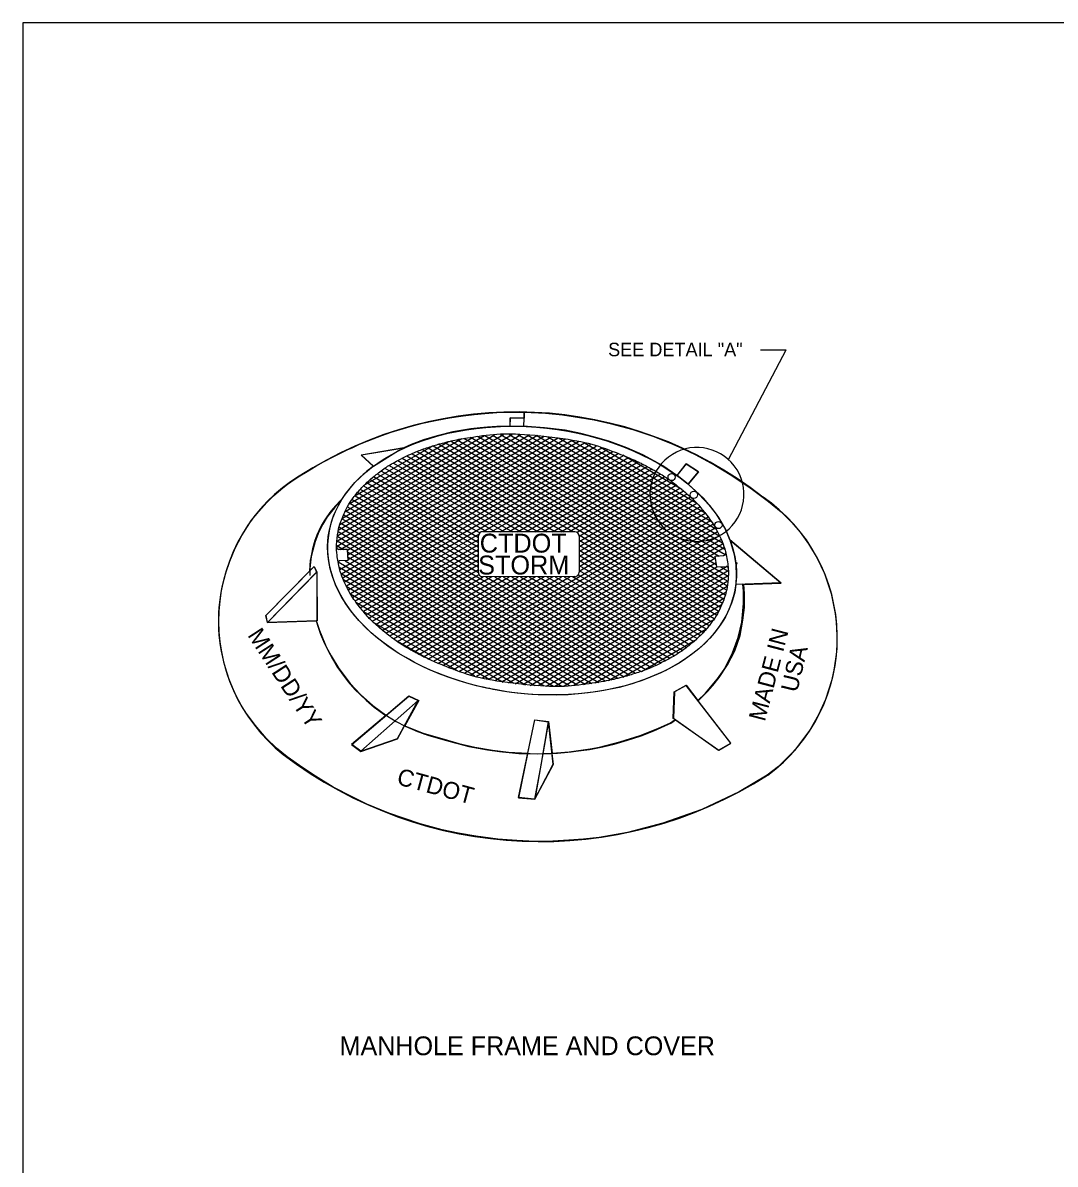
# Model space of a CAD drawing. Extents: x 0 to 31.8, y -0.5 to 20.8.
# Drawn here: x 0 to 9.62, y 10.11 to 20.75 of the extents above; entities that cross this region are included whole.
import ezdxf

# ---------------------------------------------------------------- set-up
doc = ezdxf.new("R2010")
doc.units = 0
for name, color, linetype in [('CT_Border_Perimeter_Shape', 7, 'Continuous'), ('CT_CSHT_GeneralLabel', 7, 'Continuous'), ('CT_Dimensions', 7, 'Continuous'), ('sb_Existing Structural Steel', 7, 'Continuous')]:
    doc.layers.add(name, color=color, linetype=linetype)

msp = doc.modelspace()

# ---------------------------------------------------------------- linework, layer by layer
at = {"layer": 'CT_Border_Perimeter_Shape'}
msp.add_lwpolyline([(0, 0), (31.75, 0), (31.75, 20.75), (0, 20.75)], close=True, dxfattribs=at)
at = {"layer": 'CT_Dimensions'}
for p in [(6.575, 16.68), (6.873, 17.702)]:
    msp.add_line(p, (7.113, 17.702), dxfattribs=at)
msp.add_arc((6.282, 16.354), 0.438, 31.4791, 31.418, dxfattribs=at)
at = {"layer": 'sb_Existing Structural Steel'}
for p, q in [((2.924, 15.869), (4.715, 16.908)), ((2.933, 15.923), (4.637, 16.911)), ((2.936, 15.97), (4.561, 16.913)), ((2.94, 16.02), (4.479, 16.912)), ((2.953, 16.073), (4.396, 16.91)), ((2.953, 15.654), (5.056, 16.873)), ((2.957, 15.841), (4.795, 16.907)), ((2.969, 15.614), (5.118, 16.861)), ((2.978, 16.134), (4.302, 16.902)), ((2.982, 15.576), (5.178, 16.849)), ((2.997, 15.538), (5.235, 16.835)), ((3.004, 16.196), (4.198, 16.888)), ((3.015, 15.501), (5.289, 16.82)), ((3.026, 15.836), (4.859, 16.898)), ((3.029, 15.791), (4.926, 16.892)), ((3.033, 15.746), (4.99, 16.881)), ((3.042, 16.265), (4.092, 16.874)), ((3.094, 16.342), (3.966, 16.847)), ((3.877, 16.822), (5.72, 15.756)), ((3.934, 16.837), (5.717, 15.806)), ((3.992, 16.852), (6.536, 15.379)), ((4.048, 16.864), (6.542, 15.422)), ((4.111, 16.877), (6.344, 15.585)), ((4.173, 16.887), (6.47, 15.558)), ((4.236, 16.896), (6.514, 15.578)), ((4.306, 16.902), (6.572, 15.591)), ((4.378, 16.908), (6.462, 15.702)), ((4.451, 16.913), (6.456, 15.753)), ((4.532, 16.913), (6.49, 15.78)), ((4.612, 16.913), (6.546, 15.794)), ((4.7, 16.909), (6.541, 15.844)), ((4.783, 16.908), (6.52, 15.903)), ((4.891, 16.892), (6.495, 15.965)), ((4.991, 16.881), (6.457, 16.033)), ((5.109, 16.86), (6.419, 16.102)), ((5.234, 16.834), (6.358, 16.184)), ((3.034, 15.464), (5.344, 16.804)), ((3.176, 16.436), (3.813, 16.805)), ((3.58, 16.713), (4.8, 16.007)), ((3.628, 16.734), (4.886, 16.006)), ((3.674, 16.754), (4.962, 16.009)), ((3.723, 16.772), (5.046, 16.006)), ((3.772, 16.79), (5.126, 16.007)), ((3.778, 15.851), (5.396, 16.789)), ((3.823, 16.807), (5.737, 15.7)), ((3.86, 15.853), (5.448, 16.773)), ((3.939, 15.851), (5.498, 16.755)), ((4.289, 16.007), (5.548, 16.737)), ((4.37, 16.007), (5.596, 16.718)), ((5.384, 16.794), (6.273, 16.28)), ((5.59, 16.722), (6.14, 16.404)), ((3.373, 16.6), (4.398, 16.007)), ((3.413, 16.624), (4.481, 16.007)), ((3.455, 16.647), (4.563, 16.006)), ((3.495, 16.67), (4.639, 16.009)), ((3.536, 16.693), (4.718, 16.008)), ((4.45, 16.006), (5.644, 16.699)), ((4.531, 16.007), (5.689, 16.678)), ((4.61, 16.006), (5.733, 16.657)), ((4.694, 16.007), (5.778, 16.636)), ((4.774, 16.006), (5.819, 16.613)), ((3.269, 16.52), (4.247, 15.954)), ((3.303, 16.547), (4.258, 15.995)), ((3.342, 16.572), (4.32, 16.007)), ((4.852, 16.007), (5.861, 16.592)), ((4.936, 16.006), (5.906, 16.569)), ((5.013, 16.006), (5.942, 16.545)), ((5.095, 16.007), (5.978, 16.519)), ((5.165, 16.001), (6.017, 16.495)), ((3.145, 16.404), (4.245, 15.768)), ((3.175, 16.433), (4.245, 15.815)), ((3.204, 16.464), (4.246, 15.861)), ((3.24, 16.489), (4.246, 15.907)), ((5.183, 15.916), (6.089, 16.441)), ((5.183, 15.868), (6.123, 16.414)), ((5.184, 15.964), (6.054, 16.469)), ((5.186, 15.825), (6.157, 16.388)), ((3.07, 16.306), (4.246, 15.627)), ((3.097, 16.34), (4.245, 15.676)), ((3.119, 16.372), (4.245, 15.721)), ((5.183, 15.682), (6.25, 16.3)), ((5.185, 15.73), (6.222, 16.331)), ((5.186, 15.778), (6.188, 16.359)), ((3.01, 16.201), (4.064, 15.591)), ((3.025, 16.239), (4.133, 15.598)), ((3.047, 16.273), (4.277, 15.561)), ((5.185, 15.638), (6.28, 16.273)), ((5.224, 15.61), (6.312, 16.241)), ((5.303, 15.613), (6.334, 16.211)), ((5.386, 15.613), (6.36, 16.178)), ((2.962, 16.087), (3.815, 15.593)), ((2.977, 16.127), (3.88, 15.604)), ((2.992, 16.165), (4.038, 15.559)), ((5.454, 15.604), (6.387, 16.145)), ((5.538, 15.607), (6.407, 16.111)), ((5.619, 15.607), (6.43, 16.077)), ((2.935, 15.963), (5.304, 14.593)), ((2.939, 16.008), (5.369, 14.602)), ((2.952, 16.048), (5.428, 14.615)), ((3.657, 15.641), (4.249, 15.984)), ((4.118, 14.69), (6.453, 16.044)), ((4.173, 14.674), (6.473, 16.008)), ((4.228, 14.659), (6.491, 15.971)), ((4.246, 15.627), (4.245, 15.967)), ((4.285, 16.007), (5.144, 16.007)), ((5.185, 15.966), (5.184, 15.628)), ((5.186, 15.973), (5.708, 15.671)), ((2.925, 15.877), (2.987, 15.841)), ((2.928, 15.921), (5.239, 14.584)), ((3.055, 15.432), (3.792, 15.859)), ((3.075, 15.397), (3.915, 15.884)), ((3.098, 15.363), (3.992, 15.882)), ((3.606, 15.517), (4.246, 15.888)), ((3.641, 15.585), (4.245, 15.935)), ((4.283, 14.645), (6.376, 15.859)), ((4.342, 14.631), (6.521, 15.895)), ((4.405, 14.622), (6.537, 15.858)), ((5.184, 15.927), (5.728, 15.612)), ((5.186, 15.879), (5.68, 15.594)), ((6.372, 15.857), (6.505, 15.934)), ((3.024, 15.841), (2.946, 15.842)), ((3.033, 15.738), (3.024, 15.841)), ((3.027, 15.818), (5.17, 14.578)), ((3.031, 15.768), (5.095, 14.573)), ((3.196, 15.233), (4.244, 15.841)), ((3.227, 15.204), (4.244, 15.794)), ((3.256, 15.174), (4.245, 15.747)), ((4.468, 14.611), (6.456, 15.764)), ((5.183, 15.834), (5.571, 15.61)), ((5.186, 15.784), (6.368, 15.1)), ((5.681, 15.779), (6.503, 15.304)), ((5.682, 15.826), (6.519, 15.342)), ((6.453, 15.78), (6.531, 15.784)), ((6.466, 15.678), (6.453, 15.78)), ((2.94, 15.727), (4.945, 14.567)), ((2.949, 15.675), (4.857, 14.57)), ((3.033, 15.738), (2.953, 15.735)), ((3.005, 15.736), (5.024, 14.568)), ((3.119, 15.328), (3.742, 15.69)), ((3.143, 15.296), (3.741, 15.642)), ((3.285, 15.143), (4.245, 15.7)), ((3.317, 15.116), (4.245, 15.655)), ((4.525, 14.598), (6.461, 15.72)), ((4.588, 14.588), (6.468, 15.679)), ((4.66, 14.581), (6.556, 15.681)), ((4.728, 14.574), (6.573, 15.644)), ((5.184, 15.693), (6.314, 15.04)), ((5.185, 15.646), (6.285, 15.01)), ((5.187, 15.738), (6.344, 15.068)), ((5.678, 15.641), (6.443, 15.198)), ((5.683, 15.685), (6.465, 15.233)), ((5.684, 15.731), (6.486, 15.267)), ((6.466, 15.678), (6.554, 15.681)), ((6.502, 15.679), (6.574, 15.638)), ((2.967, 15.618), (4.772, 14.574)), ((2.987, 15.56), (4.684, 14.579)), ((3.174, 15.266), (3.779, 15.617)), ((3.35, 15.087), (4.25, 15.608)), ((3.384, 15.061), (4.291, 15.587)), ((3.419, 15.035), (4.372, 15.588)), ((3.455, 15.009), (4.453, 15.587)), ((3.491, 14.983), (4.533, 15.586)), ((3.529, 14.956), (4.617, 15.587)), ((3.569, 14.932), (4.699, 15.588)), ((3.609, 14.91), (4.777, 15.588)), ((3.646, 14.886), (4.857, 15.588)), ((3.69, 14.863), (4.94, 15.588)), ((3.734, 14.841), (5.02, 15.587)), ((3.774, 14.82), (5.097, 15.587)), ((3.776, 15.616), (5.485, 14.627)), ((3.826, 14.799), (5.231, 15.614)), ((3.866, 14.779), (5.309, 15.616)), ((3.866, 15.612), (5.546, 14.641)), ((3.914, 14.76), (5.39, 15.616)), ((3.949, 15.611), (5.604, 14.653)), ((3.963, 14.74), (5.473, 15.615)), ((4.012, 14.722), (5.552, 15.615)), ((4.028, 15.612), (5.657, 14.67)), ((4.064, 14.705), (5.634, 15.615)), ((4.106, 15.614), (5.708, 14.687)), ((4.189, 15.612), (5.761, 14.702)), ((5.143, 15.588), (4.283, 15.587)), ((4.314, 15.587), (5.807, 14.723)), ((4.398, 15.587), (5.86, 14.742)), ((4.477, 15.587), (5.902, 14.763)), ((4.558, 15.587), (5.949, 14.782)), ((4.639, 15.587), (5.991, 14.804)), ((4.72, 15.587), (6.03, 14.829)), ((4.798, 15.588), (6.069, 14.853)), ((4.802, 14.572), (6.574, 15.599)), ((4.876, 14.567), (6.571, 15.55)), ((4.882, 15.587), (6.109, 14.877)), ((4.962, 15.587), (6.149, 14.9)), ((5.045, 15.587), (6.188, 14.926)), ((5.123, 15.588), (6.22, 14.953)), ((5.175, 15.605), (6.252, 14.982)), ((5.564, 15.614), (6.396, 15.133)), ((5.643, 15.615), (6.422, 15.165)), ((6.342, 15.586), (6.559, 15.461)), ((6.424, 15.585), (6.562, 15.505)), ((6.499, 15.587), (6.569, 15.547)), ((3.013, 15.498), (4.576, 14.594)), ((3.055, 15.427), (4.475, 14.605)), ((4.957, 14.566), (6.565, 15.499)), ((5.046, 14.571), (6.554, 15.446)), ((3.108, 15.348), (4.351, 14.629)), ((5.135, 14.575), (6.54, 15.39)), ((5.226, 14.582), (6.516, 15.33)), ((3.176, 15.263), (4.208, 14.666)), ((5.334, 14.597), (6.483, 15.263)), ((3.26, 15.168), (4.047, 14.713)), ((5.457, 14.62), (6.438, 15.189)), ((5.591, 14.651), (6.38, 15.109)), ((5.764, 14.705), (6.28, 15.004)), ((3.469, 15), (3.773, 14.824)), ((6.326, 14.466), (6.291, 14.433)), ((6.035, 14.223), (6.082, 14.255)), ((3.738, 14.123), (4.026, 14.04))]:
    msp.add_line(p, q, dxfattribs=at)
for points in [[(4.538, 16.991), (4.416, 16.988), (4.33, 16.981), (4.263, 16.976), (4.176, 16.965), (4.006, 16.938), (3.86, 16.901), (3.734, 16.863), (3.619, 16.819), (3.55, 16.787), (3.152, 16.72), (3.266, 16.619), (3.239, 16.597), (3.217, 16.58), (3.205, 16.57), (3.186, 16.553), (3.172, 16.54), (3.144, 16.515), (3.131, 16.503), (3.116, 16.487), (3.082, 16.452), (3.05, 16.415), (2.995, 16.343), (2.971, 16.306), (2.964, 16.3), (2.913, 16.249), (2.871, 16.198), (2.832, 16.146), (2.808, 16.109), (2.79, 16.077), (2.774, 16.048), (2.739, 15.974), (2.721, 15.925), (2.698, 15.847), (2.689, 15.798), (2.683, 15.766), (2.678, 15.741), (2.674, 15.691), (2.672, 15.64), (2.264, 15.226), (2.278, 15.16), (2.734, 15.176), (2.748, 15.125), (2.774, 15.052), (2.811, 14.965), (2.851, 14.884), (2.891, 14.811), (2.933, 14.742), (2.969, 14.691), (3.033, 14.606), (3.095, 14.536), (3.199, 14.436), (3.275, 14.371), (3.353, 14.314), (3.384, 14.293), (3.064, 14.022), (3.15, 13.958), (3.493, 14.077), (3.558, 14.197), (3.678, 14.143), (3.783, 14.108), (3.949, 14.061), (4.156, 14.005), (4.331, 13.972), (4.443, 13.957), (4.623, 13.94), (4.704, 13.937), (4.618, 13.527), (4.772, 13.513), (4.944, 13.841), (4.933, 13.94), (5.126, 13.957), (5.28, 13.978), (5.405, 14.002), (5.511, 14.027), (5.636, 14.062), (5.763, 14.105), (5.881, 14.151), (5.982, 14.196), (6.039, 14.223), (6.082, 14.252), (6.485, 13.97), (6.599, 14.036), (6.293, 14.431), (6.362, 14.498), (6.429, 14.572), (6.488, 14.647), (6.567, 14.765), (6.634, 14.897), (6.684, 15.038), (6.71, 15.181), (6.724, 15.3), (6.726, 15.432), (6.718, 15.515), (7.068, 15.528), (6.59, 15.931), (6.565, 15.992), (6.549, 16.027), (6.528, 16.064), (6.464, 16.169), (6.408, 16.242), (6.345, 16.315), (6.27, 16.389), (6.201, 16.45), (6.297, 16.565), (6.181, 16.64), (6.096, 16.532), (5.965, 16.62), (5.886, 16.665), (5.778, 16.722), (5.63, 16.788), (5.47, 16.846), (5.351, 16.881), (5.2, 16.921), (5.053, 16.952), (4.862, 16.976), (4.741, 16.985), (4.668, 16.989), (4.671, 17.063), (4.673, 17.122), (4.87, 17.113), (5.03, 17.096), (5.129, 17.082), (5.325, 17.048), (5.472, 17.016), (5.683, 16.958), (5.879, 16.894), (6.058, 16.822), (6.147, 16.783), (6.266, 16.727), (6.448, 16.627), (6.593, 16.539), (6.746, 16.437), (6.801, 16.399), (6.95, 16.287), (7.068, 16.191), (7.167, 16.091), (7.245, 16.003), (7.323, 15.893), (7.402, 15.76), (7.47, 15.617), (7.533, 15.43), (7.57, 15.245), (7.58, 15.164), (7.587, 15.042), (7.585, 14.916), (7.577, 14.839), (7.559, 14.716), (7.536, 14.617), (7.48, 14.444), (7.415, 14.301), (7.333, 14.156), (7.192, 13.968), (7.041, 13.819), (6.937, 13.736), (6.675, 13.583), (6.326, 13.418), (5.963, 13.29), (5.635, 13.203), (5.371, 13.157), (5.226, 13.142), (5.087, 13.13), (4.889, 13.12), (4.716, 13.122), (4.603, 13.128), (4.426, 13.141), (4.221, 13.168), (4.058, 13.197), (3.909, 13.228), (3.702, 13.284), (3.411, 13.384), (3.205, 13.468), (3.076, 13.532), (2.892, 13.625), (2.727, 13.729), (2.608, 13.805), (2.464, 13.907), (2.364, 13.99), (2.269, 14.083), (2.164, 14.204), (2.075, 14.325), (2.035, 14.389), (1.988, 14.477), (1.962, 14.534), (1.932, 14.607), (1.911, 14.663), (1.889, 14.735), (1.869, 14.808), (1.851, 14.892), (1.842, 14.945), (1.836, 14.994), (1.83, 15.046), (1.827, 15.099), (1.826, 15.145), (1.825, 15.184), (1.827, 15.246), (1.831, 15.3), (1.836, 15.349), (1.848, 15.439), (1.861, 15.506), (1.891, 15.623), (1.928, 15.732), (1.979, 15.854), (2.041, 15.97), (2.13, 16.113), (2.198, 16.194), (2.274, 16.279), (2.337, 16.342), (2.405, 16.401), (2.466, 16.449), (2.53, 16.494), (2.581, 16.526), (2.634, 16.56), (2.729, 16.616), (2.803, 16.658), (2.891, 16.706), (2.965, 16.743), (3.021, 16.77), (3.075, 16.793), (3.136, 16.822), (3.21, 16.851), (3.264, 16.873), (3.345, 16.904), (3.432, 16.933), (3.515, 16.959), (3.61, 16.987), (3.725, 17.017), (3.845, 17.044), (3.975, 17.068), (4.102, 17.087), (4.206, 17.099), (4.306, 17.109), (4.416, 17.118), (4.509, 17.121), (4.577, 17.121), (4.649, 17.121), (4.672, 17.122), (4.671, 17.064), (4.54, 17.067)], [(4.54, 16.991), (4.541, 17.067), (4.669, 17.064), (4.667, 16.988)], [(3.156, 16.72), (3.267, 16.619), (3.501, 16.763), (3.549, 16.786), (3.328, 16.748)], [(6.097, 16.53), (6.18, 16.639), (6.295, 16.564), (6.199, 16.451)], [(2.958, 16.288), (2.904, 16.23), (2.836, 16.144), (2.795, 16.078), (2.759, 16.005), (2.723, 15.915), (2.701, 15.836), (2.688, 15.776), (2.681, 15.724), (2.676, 15.661), (2.676, 15.645), (2.715, 15.683), (2.739, 15.628), (2.742, 15.176), (2.735, 15.176), (2.74, 15.16), (2.75, 15.128), (2.763, 15.091), (2.779, 15.047), (2.827, 14.935), (2.872, 14.849), (2.945, 14.73), (3.049, 14.593), (3.148, 14.489), (3.262, 14.386), (3.381, 14.301), (3.387, 14.298), (3.596, 14.477), (3.69, 14.434), (3.56, 14.198), (3.73, 14.129), (3.905, 14.079), (4.064, 14.033), (4.211, 13.999), (4.378, 13.97), (4.527, 13.951), (4.706, 13.941), (4.77, 14.254), (4.9, 14.237), (4.932, 13.942), (5.092, 13.955), (5.286, 13.982), (5.373, 13.999), (5.562, 14.047), (5.753, 14.107), (5.923, 14.174), (6.037, 14.224), (6.079, 14.255), (6.061, 14.266), (6.071, 14.514), (6.181, 14.575), (6.291, 14.434), (6.363, 14.503), (6.475, 14.634), (6.536, 14.723), (6.562, 14.771), (6.614, 14.876), (6.667, 15.022), (6.701, 15.163), (6.717, 15.336), (6.716, 15.452), (6.71, 15.517), (6.645, 15.515), (6.634, 15.443), (6.628, 15.42), (6.613, 15.37), (6.604, 15.34), (6.59, 15.304), (6.568, 15.252), (6.547, 15.213), (6.529, 15.182), (6.499, 15.135), (6.45, 15.069), (6.427, 15.041), (6.404, 15.017), (6.358, 14.969), (6.301, 14.916), (6.245, 14.871), (6.155, 14.806), (6.11, 14.779), (6.021, 14.727), (5.946, 14.69), (5.819, 14.637), (5.678, 14.588), (5.557, 14.555), (5.415, 14.525), (5.316, 14.51), (5.206, 14.497), (5.083, 14.487), (4.971, 14.484), (4.839, 14.485), (4.743, 14.49), (4.676, 14.496), (4.555, 14.509), (4.47, 14.521), (4.402, 14.533), (4.382, 14.537), (4.351, 14.544), (4.326, 14.548), (4.29, 14.557), (4.257, 14.564), (4.219, 14.574), (4.171, 14.586), (4.127, 14.598), (4.066, 14.617), (4.01, 14.635), (3.917, 14.668), (3.789, 14.719), (3.719, 14.753), (3.649, 14.788), (3.602, 14.814), (3.546, 14.846), (3.505, 14.871), (3.415, 14.93), (3.361, 14.972), (3.313, 15.009), (3.269, 15.044), (3.204, 15.104), (3.13, 15.179), (3.057, 15.269), (3.011, 15.333), (2.975, 15.392), (2.95, 15.438), (2.915, 15.513), (2.89, 15.579), (2.865, 15.661), (2.852, 15.728), (2.842, 15.801), (2.84, 15.871), (2.846, 15.962), (2.858, 16.025), (2.876, 16.098), (2.896, 16.154), (2.911, 16.19), (2.931, 16.231), (2.95, 16.268)], [(6.648, 15.698), (6.633, 15.791), (6.592, 15.928), (7.065, 15.53), (6.646, 15.516), (6.651, 15.601), (6.648, 15.695), (6.658, 15.718)], [(2.279, 15.16), (2.266, 15.226), (2.714, 15.681), (2.738, 15.628)], [(2.279, 15.16), (2.739, 15.629), (2.741, 15.177)], [(3.149, 13.96), (3.067, 14.023), (3.597, 14.474), (3.685, 14.433)], [(6.073, 14.513), (6.063, 14.268), (6.484, 13.97), (6.597, 14.036), (6.181, 14.573)], [(3.493, 14.08), (3.685, 14.433), (3.149, 13.96)], [(4.828, 13.831), (4.769, 13.514), (4.619, 13.528), (4.771, 14.253), (4.895, 14.235)], [(4.942, 13.84), (4.898, 14.237), (4.77, 13.515)]]:
    msp.add_lwpolyline(points, close=True, dxfattribs=at)
for centre in [(6.046, 16.516), (6.253, 16.35), (6.482, 16.069)]:
    msp.add_circle(centre, 0.0336, dxfattribs=at)
for centre, radius, start, end in [((4.6, 13.406), 3.717, 51.8408, 122.9926), ((3.411, 15.176), 1.587, 121.7479, 231.6718), ((3.597, 15.623), 0.924, 132.7102, 181.6199), ((6.002, 15.017), 1.588, 306.291, 55.652), ((4.286, 15.967), 0.0401, 90.2279, 180.2279), ((5.144, 15.966), 0.0405, 0, 90), ((2.946, 15.863), 0.0214, 177.9097, 269.8107), ((6.529, 15.806), 0.0216, 273.8423, 5.7433), ((2.953, 15.721), 0.0139, 88.8359, 189.9123), ((6.557, 15.666), 0.0157, 358.5017, 99.578), ((4.284, 15.625), 0.0384, 177.4725, 267.4725), ((5.143, 15.628), 0.0405, 270, 0), ((5.476, 15.374), 1.245, 313.1042, 6.5278), ((4.242, 15.607), 1.567, 196.2474, 251.2608), ((4.789, 16.797), 2.86, 254.5412, 295.8297), ((4.822, 17.051), 3.933, 232.4875, 302.5979)]:
    msp.add_arc(centre, radius, start, end, dxfattribs=at)
msp.add_ellipse((4.746, 15.737), major_axis=(1.899, -0.213), ratio=0.649841, dxfattribs=at)
msp.add_open_spline([(6.57, 15.537), (6.578, 15.61), (6.575, 15.685), (6.547, 15.833), (6.522, 15.908), (6.468, 16.019), (6.447, 16.055), (6.399, 16.128), (6.373, 16.164), (6.286, 16.271), (6.217, 16.338), (6.062, 16.466), (5.975, 16.526), (5.857, 16.594), (5.833, 16.607), (5.783, 16.633), (5.758, 16.646), (5.681, 16.682), (5.629, 16.705), (5.359, 16.811), (5.122, 16.869), (4.636, 16.924), (4.392, 16.92), (4.106, 16.876), (4.049, 16.866), (3.967, 16.847), (3.939, 16.84), (3.885, 16.826), (3.859, 16.818), (3.728, 16.778), (3.63, 16.739), (3.45, 16.649), (3.369, 16.598), (3.26, 16.514), (3.226, 16.484), (3.164, 16.424), (3.135, 16.393), (3.058, 16.297), (3.017, 16.229), (2.957, 16.091), (2.937, 16.019), (2.921, 15.873), (2.924, 15.799), (2.952, 15.65), (2.977, 15.575), (3.031, 15.464), (3.052, 15.428), (3.099, 15.355), (3.126, 15.319), (3.213, 15.213), (3.281, 15.145), (3.437, 15.017), (3.523, 14.957), (3.642, 14.889), (3.666, 14.876), (3.716, 14.85), (3.741, 14.837), (3.818, 14.801), (3.87, 14.778), (4.14, 14.672), (4.377, 14.614), (4.863, 14.559), (5.107, 14.563), (5.393, 14.607), (5.449, 14.617), (5.532, 14.636), (5.56, 14.643), (5.614, 14.657), (5.64, 14.665), (5.771, 14.705), (5.869, 14.744), (6.049, 14.834), (6.13, 14.885), (6.239, 14.969), (6.273, 14.999), (6.335, 15.059), (6.364, 15.09), (6.441, 15.187), (6.482, 15.254), (6.542, 15.392), (6.561, 15.464), (6.57, 15.537)], degree=3, dxfattribs=at)

# ---------------------------------------------------------------- texts
at = {"layer": 'CT_CSHT_GeneralLabel'}
for s, rotation, p in [('MM/DD/YY', 303.0555, (2.089, 15.042)), ('MADE IN', 75.3637, (6.915, 14.231)), ('USA', 76.5262, (7.215, 14.502)), ('CTDOT', 344.7877, (3.476, 13.654))]:
    msp.add_text(s, height=0.1576, rotation=rotation, dxfattribs=at).set_placement(p)
msp.add_text('MANHOLE FRAME AND COVER', height=0.175, dxfattribs=at).set_placement((2.952, 11.127))
at = {"layer": 'CT_Dimensions'}
msp.add_text('SEE DETAIL "A"', height=0.1261, dxfattribs=at).set_placement((5.454, 17.642))
at = {"layer": 'sb_Existing Structural Steel'}
for s, p in [('CTDOT', (4.258, 15.812)), ('STORM', (4.243, 15.608))]:
    msp.add_text(s, height=0.176, dxfattribs=at).set_placement(p)

doc.saveas('drawing.dxf')
